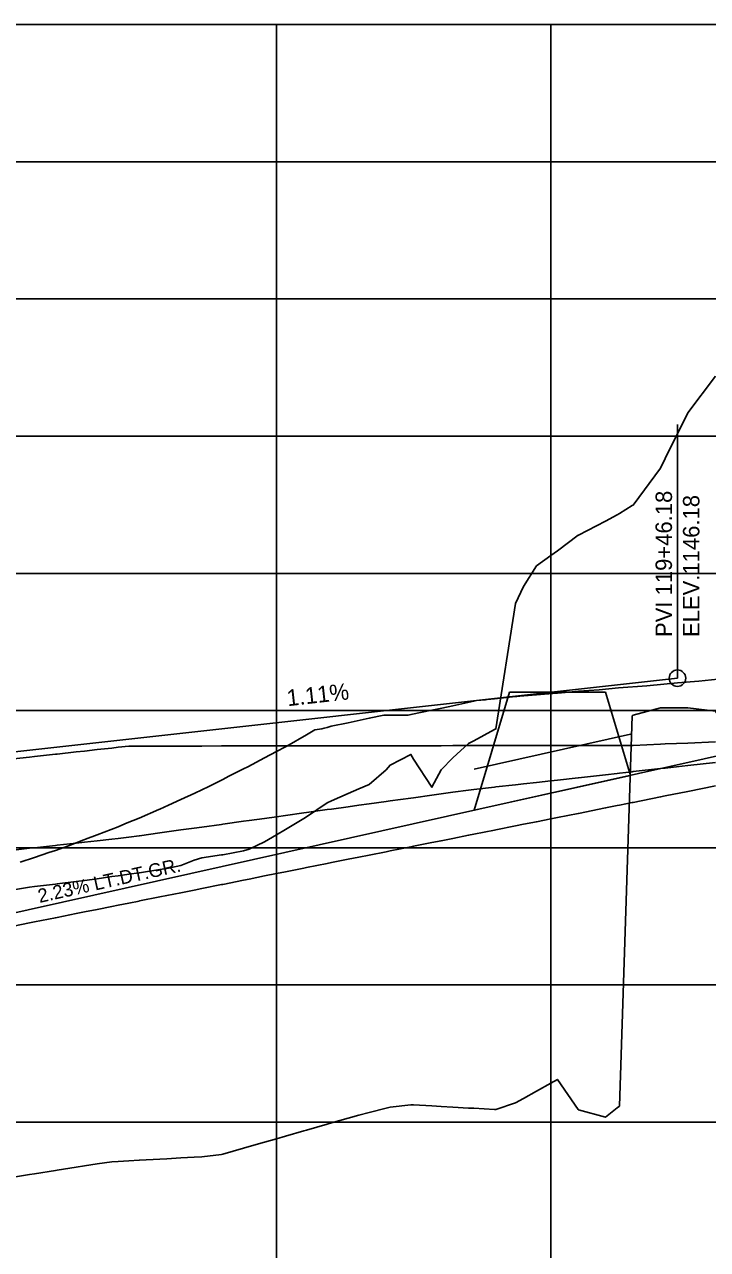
# Model space of a CAD drawing. Extents: x 688474 to 694748, y 765018 to 767373.
# Drawn here: x 692661.7 to 692910.7, y 765913.5 to 766359.9 of the extents above; entities that cross this region are included whole.
import ezdxf

# ---------------------------------------------------------------- set-up
doc = ezdxf.new("R2010")
doc.units = 0
for name, color, linetype in [('37', 7, 'Continuous'), ('R_Exist Surface', 7, 'Continuous'), ('R_No Plot', 7, 'Continuous'), ('R_Profile Work Left', 7, 'Continuous'), ('R_Profile Work Right', 7, 'Continuous'), ('R_Vert Alg', 7, 'Continuous'), ('R_Vert Alg Annot', 7, 'Continuous')]:
    doc.layers.add(name, color=color, linetype=linetype)

msp = doc.modelspace()

# ---------------------------------------------------------------- linework, layer by layer
at = {"layer": '37'}
for p, q in [((690853.59, 766359.92), (693453.59, 766359.92)), ((690853.59, 766359.92), (693453.59, 766359.92)), ((692753.59, 765809.92), (692753.59, 766359.92)), ((692853.59, 765809.92), (692853.59, 766359.92)), ((690853.59, 766309.92), (693453.59, 766309.92)), ((690853.59, 766259.92), (693453.59, 766259.92)), ((690853.59, 766209.92), (693453.59, 766209.92)), ((690853.59, 766159.92), (693453.59, 766159.92)), ((690853.59, 766109.92), (693453.59, 766109.92)), ((690853.59, 766059.92), (693453.59, 766059.92)), ((690853.59, 766009.92), (693453.59, 766009.92)), ((690853.59, 765959.92), (693453.59, 765959.92))]:
    msp.add_line(p, q, dxfattribs=at)
at = {"layer": 'R_Exist Surface'}
msp.add_lwpolyline([(692660.09, 766054.67), (692665.34, 766056.37), (692670.6, 766058.14), (692671.84, 766058.61), (692672.96, 766058.98), (692677.8, 766060.63), (692680.59, 766061.71), (692683.32, 766062.81), (692683.95, 766063.07), (692688.22, 766064.64), (692695.84, 766067.57), (692697.21, 766068.12), (692699.18, 766069.01), (692703.47, 766070.75), (692710.71, 766073.8), (692711.09, 766073.99), (692714.17, 766075.49), (692718.72, 766077.52), (692723.76, 766079.84), (692726.35, 766081.07), (692728.86, 766082.3), (692733.97, 766084.81), (692736.22, 766085.95), (692741.6, 766088.63), (692743.14, 766089.43), (692749.23, 766092.64), (692753.61, 766095.03), (692756.85, 766096.67), (692757.33, 766096.92), (692764.48, 766101.03), (692767.62, 766102.9), (692770.07, 766103.28), (692771, 766103.44), (692772.11, 766103.77), (692773.47, 766104.18), (692779.73, 766105.49), (692787.36, 766107.12), (692787.37, 766107.12), (692792.67, 766108.23), (692794.99, 766108.23), (692797.8, 766108.22), (692801.59, 766108.25), (692802.61, 766108.45), (692806.75, 766109.32), (692810.24, 766110.02), (692813.85, 766110.76), (692817.87, 766111.63), (692825.49, 766113.3), (692826.56, 766113.54), (692829.78, 766113.83), (692830.43, 766113.89), (692833.12, 766114.18), (692840.75, 766115), (692841.23, 766115.06), (692841.94, 766115.14), (692842.34, 766115.18), (692848.37, 766115.66), (692855.78, 766116.24), (692856, 766116.26), (692860.26, 766116.67), (692863.63, 766116.93), (692871.24, 766117.51), (692878.23, 766118.2), (692888.6, 766118.92), (692899.81, 766120.07), (692907.58, 766120.64), (692921.38, 766122.11)], dxfattribs=at)
at = {"layer": 'R_No Plot'}
for p, q in [((692838.59, 766116.62), (692825.68, 766073.6)), ((692873.59, 766116.62), (692838.59, 766116.62)), ((692873.59, 766116.62), (692882.68, 766086.31)), ((692825.68, 766088.6), (692882.68, 766101.31)), ((692825.68, 766073.6), (692882.68, 766086.31))]:
    msp.add_line(p, q, dxfattribs=at)
at = {"layer": 'R_Profile Work Left'}
for points in [[(692657.71, 766044.64), (692663.59, 766045.55), (692665.34, 766045.75), (692672.96, 766046.67), (692673.59, 766046.74), (692680.59, 766047.63), (692683.59, 766048.02), (692688.22, 766048.64), (692693.59, 766049.4), (692695.84, 766049.71), (692699.77, 766050.24), (692703.47, 766050.77), (692703.59, 766050.79), (692711.09, 766051.94), (692713.59, 766052.42), (692718.72, 766053.47), (692723.59, 766055.37), (692726.35, 766056.19), (692733.59, 766057.34), (692733.97, 766057.4), (692741.6, 766058.77), (692743.59, 766059.44), (692749.23, 766062.04), (692753.59, 766064.6), (692756.85, 766066.52), (692763.59, 766070.59), (692764.48, 766071.19), (692772.11, 766076.33), (692773.59, 766077), (692779.73, 766079.63), (692783.59, 766081.34), (692787.36, 766083.02), (692793.59, 766088.33), (692794.99, 766090.02), (692802.61, 766093.94), (692803.59, 766092.26), (692810.24, 766081.98), (692813.59, 766088.31), (692817.87, 766092.68), (692823.59, 766097.87), (692825.49, 766098.87), (692833.12, 766102.98), (692833.59, 766103.24), (692840.75, 766148.9), (692843.59, 766155.15), (692848.37, 766162.64), (692853.59, 766166.44), (692856, 766168.06), (692863.59, 766173.86), (692863.63, 766173.88), (692873.59, 766178.99), (692877.78, 766181.19), (692878.59, 766181.69), (692883.27, 766184.61), (692883.59, 766184.81), (692893.59, 766198.25), (692895.28, 766201.81), (692903.59, 766218.43), (692913.59, 766231.76)], [(692657.71, 766092.28), (692663.59, 766092.93), (692665.34, 766093.13), (692672.96, 766093.97), (692673.59, 766094.04), (692680.59, 766094.82), (692683.59, 766095.16), (692688.22, 766095.67), (692693.59, 766096.27), (692695.84, 766096.52), (692699.77, 766096.96), (692703.47, 766096.96), (692703.59, 766096.96), (692711.09, 766096.98), (692713.59, 766096.98), (692718.72, 766096.99), (692723.59, 766096.99), (692726.35, 766097), (692733.59, 766097.01), (692733.97, 766097.01), (692741.6, 766097.02), (692743.59, 766097.02), (692749.23, 766097.03), (692753.59, 766097.04), (692756.85, 766097.04), (692763.59, 766097.05), (692764.48, 766097.05), (692772.11, 766097.06), (692773.59, 766097.07), (692779.73, 766097.07), (692783.59, 766097.08), (692787.36, 766097.09), (692793.59, 766097.09), (692794.99, 766097.1), (692802.61, 766097.11), (692803.59, 766097.11), (692810.24, 766097.12), (692813.59, 766097.12), (692817.87, 766097.13), (692823.59, 766097.14), (692825.49, 766097.14), (692833.12, 766097.15), (692833.59, 766097.15), (692840.75, 766097.16), (692843.59, 766097.17), (692848.37, 766097.17), (692853.59, 766097.18), (692856, 766097.19), (692863.59, 766097.2), (692863.63, 766097.2), (692873.59, 766097.21), (692877.78, 766097.22), (692878.59, 766097.22), (692883.27, 766097.22), (692883.59, 766097.24), (692893.59, 766097.66), (692895.28, 766097.74), (692903.59, 766098.09), (692913.59, 766098.52)], [(692657.71, 766031.36), (692663.59, 766032.54), (692665.34, 766032.88), (692672.96, 766034.41), (692673.59, 766034.53), (692680.59, 766035.93), (692683.59, 766036.53), (692688.22, 766037.45), (692693.59, 766038.52), (692695.84, 766038.97), (692699.77, 766039.76), (692703.47, 766040.5), (692703.59, 766040.52), (692711.09, 766042.02), (692713.59, 766042.52), (692718.72, 766043.54), (692723.59, 766044.51), (692726.35, 766045.06), (692733.59, 766046.51), (692733.97, 766046.59), (692741.6, 766048.11), (692743.59, 766048.5), (692749.23, 766049.63), (692753.59, 766050.5), (692756.85, 766051.15), (692763.59, 766052.5), (692764.48, 766052.67), (692772.11, 766054.2), (692773.59, 766054.49), (692779.73, 766055.72), (692783.59, 766056.49), (692787.36, 766057.24), (692793.59, 766058.48), (692794.99, 766058.76), (692802.61, 766060.29), (692803.59, 766060.48), (692810.24, 766061.81), (692813.59, 766062.48), (692817.87, 766063.33), (692823.59, 766064.47), (692825.49, 766064.85), (692833.12, 766066.37), (692833.59, 766066.47), (692840.75, 766067.9), (692843.59, 766068.46), (692848.37, 766069.42), (692853.59, 766070.46), (692856, 766070.94), (692863.59, 766072.46), (692863.63, 766072.46), (692873.59, 766074.45), (692877.78, 766075.29), (692878.59, 766075.45), (692883.27, 766076.38), (692883.59, 766076.45), (692893.59, 766078.44), (692895.28, 766078.78), (692903.59, 766080.44), (692913.59, 766082.44)]]:
    msp.add_lwpolyline(points, dxfattribs=at)
at = {"layer": 'R_Profile Work Right'}
for points in [[(692883.27, 766108.04), (692883.59, 766108.18), (692893.59, 766110.91), (692895.28, 766110.92), (692903.59, 766110.95), (692913.59, 766109.67), (692923.59, 766093.03)], [(692657.71, 765939.88), (692663.59, 765940.8), (692665.34, 765941.08), (692672.96, 765942.28), (692673.59, 765942.37), (692680.59, 765943.48), (692683.59, 765943.95), (692688.22, 765944.68), (692693.59, 765945.47), (692695.84, 765945.6), (692699.77, 765945.82), (692703.47, 765946.02), (692703.59, 765946.03), (692711.09, 765946.45), (692713.59, 765946.59), (692718.72, 765946.88), (692723.59, 765947.15), (692726.35, 765947.31), (692733.59, 765948.15), (692733.97, 765948.26), (692741.6, 765950.44), (692743.59, 765951.01), (692749.23, 765952.63), (692753.59, 765953.88), (692756.85, 765954.82), (692763.59, 765956.76), (692764.48, 765957.02), (692772.11, 765959.22), (692773.59, 765959.65), (692779.73, 765961.43), (692783.59, 765962.48), (692787.36, 765963.44), (692793.59, 765965.03), (692794.99, 765965.38), (692802.61, 765966.26), (692803.59, 765966.2), (692810.24, 765965.83), (692813.59, 765965.64), (692817.87, 765965.4), (692823.59, 765965.08), (692825.49, 765964.97), (692833.12, 765964.55), (692833.59, 765964.52), (692840.75, 765966.99), (692843.59, 765968.58), (692848.37, 765971.25), (692853.59, 765974.15), (692856, 765975.49), (692863.59, 765964.55), (692863.63, 765964.47), (692873.59, 765961.75), (692877.78, 765965.14), (692878.59, 765965.8), (692883.27, 766108.04)], [(692657.71, 766059.08), (692663.59, 766059.73), (692665.34, 766059.93), (692672.96, 766060.77), (692673.59, 766060.84), (692680.59, 766061.62), (692683.59, 766061.96), (692688.22, 766062.47), (692693.59, 766063.07), (692695.84, 766063.32), (692699.77, 766063.76), (692703.47, 766064.27), (692703.59, 766064.29), (692711.09, 766065.33), (692713.59, 766065.68), (692718.72, 766066.39), (692723.59, 766067.06), (692726.35, 766067.45), (692733.59, 766068.45), (692733.97, 766068.51), (692741.6, 766069.56), (692743.59, 766069.84), (692749.23, 766070.62), (692753.59, 766071.23), (692756.85, 766071.68), (692763.59, 766072.62), (692764.48, 766072.74), (692772.11, 766073.8), (692773.59, 766074), (692779.73, 766074.86), (692783.59, 766075.39), (692787.36, 766075.91), (692793.59, 766076.78), (692794.99, 766076.97), (692802.61, 766078.03), (692803.59, 766078.17), (692810.24, 766079.09), (692813.59, 766079.55), (692817.87, 766080.15), (692823.59, 766080.94), (692825.49, 766081.19), (692833.12, 766082.04), (692833.59, 766082.09), (692840.75, 766082.89), (692843.59, 766083.21), (692848.37, 766083.74), (692853.59, 766084.32), (692856, 766084.59), (692863.59, 766085.43), (692863.63, 766085.44), (692873.59, 766086.55), (692877.78, 766087.01), (692878.59, 766087.1), (692883.27, 766087.62), (692883.59, 766087.66), (692893.59, 766088.77), (692895.28, 766088.96), (692903.59, 766089.89), (692913.59, 766091)]]:
    msp.add_lwpolyline(points, dxfattribs=at)
at = {"layer": 'R_Vert Alg'}
for p, q in [((692643.59, 766093.22), (692899.77, 766121.72)), ((692503.54, 766001.76), (692951.23, 766101.59))]:
    msp.add_line(p, q, dxfattribs=at)
msp.add_circle((692899.77, 766121.72), 3, dxfattribs=at)
at = {"layer": 'R_Vert Alg Annot'}
msp.add_line((692899.77, 766121.72), (692899.77, 766214.12), dxfattribs=at)

# ---------------------------------------------------------------- texts
for s, height, rotation, p in [('PVI 119+46.18', 6, 90, (692897.77, 766136.72)), ('ELEV.1146.18', 6, 90, (692907.77, 766136.72)), ('1.11%', 6, 6.3516, (692757.68, 766111.49)), ('2.23% LT.DT.GR.', 5, 12.5713, (692667.19, 766039.79))]:
    msp.add_text(s, height=height, rotation=rotation, dxfattribs=at).set_placement(p)

doc.saveas('drawing.dxf')
